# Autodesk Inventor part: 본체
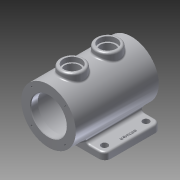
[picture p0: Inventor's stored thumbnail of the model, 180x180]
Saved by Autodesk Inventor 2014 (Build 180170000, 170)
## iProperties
Created: 2014-12
Part Number: 본체
Material: 알루미늄 6061
Document SubType Name: Modeling
Designer: Owner
Mass: 1293.94 g
Surface Area: 1039.34 cm^2
Volume: 477.47 cm^3
Density: 2.71 g/cm^3
Appearance: 알루미늄 - 평지
Author: Owner
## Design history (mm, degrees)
sketch "스케치1"
  geometry: C1 r 46 at (0, 0); 1 further point
  constraints: 1 centre point, 1 coincident
  dimensions: "d0" = 92 diameter of C1
extrude "돌출1" new body sketch "스케치1" stored distance "d1" = 140; taper "d2" = 0 deg
sketch "스케치2"
  geometry: C1 r 46 at (0, 0) reference; 1 further point
  constraints: 1 coincident
hole "구멍1" sketch "스케치2" at (0, 0) diameter "d3" = 60; stored, may be unused: countersink angle "d7" = 90 deg, drill point angle "d9" = 0 deg; dims "d4" = 6, "d5" = 4, "d6" = 2, "d8" = 12
sketch "스케치3"
  geometry: C1 r 30 at (0, 0) reference; 1 further point
  constraints: 1 coincident
hole "구멍2" sketch "스케치3" at (0, 0) diameter "d10" = 75; stored, may be unused: countersink angle "d14" = 90 deg, drill point angle "d16" = 0 deg; dims "d11" = 6, "d12" = 4, "d13" = 2, "d15" = 58
node "작업 평면1"
node "작업 평면2"
sketch "스케치11"
  geometry: L1 (-65, -40)-(65, -40); L2 (65, -40)-(65, 55); L3 (65, 55)-(-65, 55); L4 (-65, 55)-(-65, -40); 2 further points
  constraints: 8 end point, 2 parallel, 1 horizontal, 1 midpoint, 1 perpendicular, 1 vertical alignment
  dimensions: "d44" = 40 distance from line of L1 point (0, 0); "d45" = 55 distance from line of L3 point (0, 0); "d46" = 130 distance of L2.end L3.end
extrude "돌출4" join sketch "스케치11" distance "d47" = 12; taper "d48" = 0 deg
sketch "스케치12"
  geometry: L1 (25.923, -40)-(65, -40) reference; L2 (65, -40)-(65, 55) reference; 2 further points
  constraints: 1 other
  dimensions: "d49" = 47.5 distance from line of point (57, 7.5) L1; "d50" = 8 distance from line of L2 point (57, 7.5)
feature "엠보싱1" sketch "스케치12" dims "d2" = 0, "d44" = 40, "d45" = 55, "d46" = 130, "d51" = 1, "d52" = 0
sketch "스케치13"
  geometry: L1 (25.923, -40)-(65, -40) reference; L2 (65, -40)-(65, 55) reference; 2 further points
  dimensions: "d53" = 13 distance from line of point (52, -27.5) L2; "d54" = 12.5 distance from line of point (52, -27.5) L1
hole "구멍5" sketch "스케치13" at (52, -27.5) diameter "d55" = 11; stored, may be unused: countersink angle "d59" = 90 deg, drill point angle "d61" = 0 deg; dims "d56" = 6, "d57" = 4, "d58" = 2, "d60" = 50
sketch "스케치14"
  geometry: L1 (0, 0)-(28.284, 28.284); L2 (0, 0)-(40, 0); C1 r 46 at (0, 0) reference; 1 further point
  constraints: 4 end point, 1 coincident, 1 equal length, 1 horizontal
  dimensions: "d68" = 40 distance of L1.start L1.end; "d69" = 45 deg angle of L2 L1
hole "구멍6" sketch "스케치14" at (28.284, 28.284) diameter "d70" = 3.242; stored, may be unused: countersink angle "d74" = 90 deg, drill point angle "d76" = 118 deg; dims "d71" = 8, "d72" = 4, "d73" = 2, "d75" = 10
fillet "모깎기2" dims "d81" = 5
fillet "모깎기5" dims "d84" = 3
fillet "모깎기6" dims "d85" = 10
fillet "모깎기7" dims "d86" = 3
chamfer "모따기1" distance "d87" = 1; stored, may be unused: second distance "d88" = 2, angle "d89" = 45 deg
fillet "모깎기8" dims "d90" = 3
node "작업 평면4"
  node "작업 평면3"
sketch "스케치16"
  geometry: L1 (-35.072, 58)-(-35.072, -43) reference; L2 (35.072, -43)-(-35.072, -43) reference; L3 (35.072, -43)-(35.072, 58) reference; L4 (-35.072, 58)-(35.072, 58) reference; L5 (-46, -70)-(46, -70) reference; L6 (46, 70)-(-46, 70) reference; C1 r 20 at (0, 30); C2 r 20 at (0, -30); 1 further point
  constraints: 2 centre point, 2 vertical alignment, 1 equal radius
  dimensions: "d93" = 40 distance from line of C1.centre L6; "d94" = 60 distance of C2.centre C1.centre; "d95" = 40 diameter of C1
extrude "돌출5" join sketch "스케치16" stored distance "d96" = 10; taper "d97" = 0 deg
sketch "스케치17"
  geometry: C1 r 20 at (0, 0) reference; C2 r 15 at (0, 0); 1 further point
  constraints: 1 centre point, 1 coincident
  dimensions: "d98" = 30 diameter of C2
extrude "돌출6" cut sketch "스케치17" distance "d99" = 8; taper "d100" = 0 deg
sketch "스케치18"
  geometry: C1 r 15 at (0, 0) reference; C2 r 12.5 at (0, 0); 1 further point
  constraints: 1 centre point, 1 coincident
  dimensions: "d101" = 25 diameter of C2
extrude "돌출7" cut sketch "스케치18" stored distance "d102" = 8; taper "d103" = 0 deg
fillet "모깎기9" dims "d104" = 3
node "솔리드1"
mirror "대칭1"
pattern_linear "직사각형 패턴1" dims "d64" = 70, "d67" = 104
pattern_circular "원형 패턴1" dims angle "d78" = 360 deg
mirror "대칭3"
mirror "대칭4"
node "투영된 루프1"
other parameters: "d17" = 54, "d92" = 106
